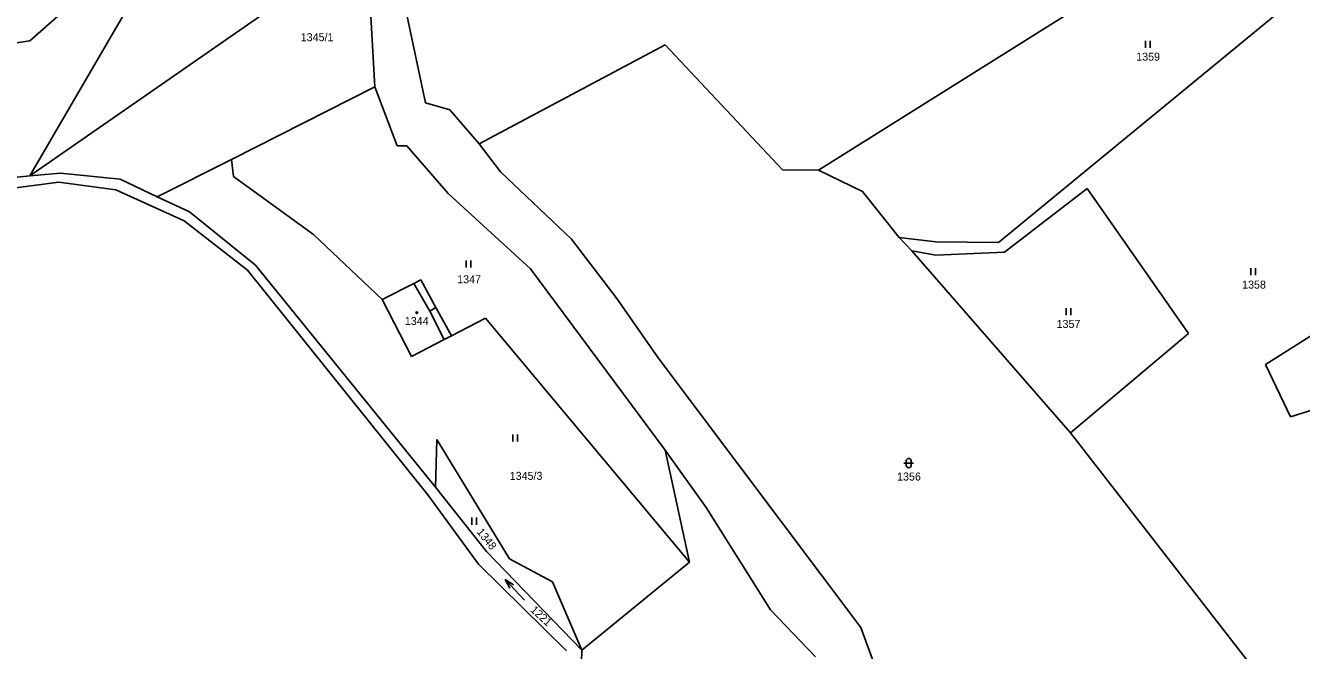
# Model space of a CAD drawing. Extents: x -670359 to -668019, y -978807 to -976674.
# Drawn here: x -669846.5 to -669575.5, y -978251.2 to -978118.6 of the extents above; entities that cross this region are included whole.
import ezdxf

# ---------------------------------------------------------------- set-up
doc = ezdxf.new("R2010")
doc.units = 0
for name, color, linetype in [('Hranice kat_území', 7, 'Continuous'), ('Hranice parcel', 7, 'Continuous'), ('Parcelní čísla', 7, 'Continuous'), ('Vnitřní kresba', 7, 'Continuous'), ('Značky budov', 7, 'Continuous'), ('Značky kultur', 7, 'Continuous')]:
    doc.layers.add(name, color=color, linetype=linetype)

msp = doc.modelspace()

# ---------------------------------------------------------------- linework, layer by layer
at = {"layer": 'Hranice kat_území'}
for points in [[(-669877.35, -978156.82), (-669839.43, -978151.83)], [(-669839.43, -978151.83), (-669827.35, -978153.5)], [(-669827.35, -978153.5), (-669812.86, -978160.03)], [(-669812.86, -978160.03), (-669799.41, -978170.5)], [(-669799.41, -978170.5), (-669761.06, -978218.21)], [(-669761.06, -978218.21), (-669750.32, -978232.95)], [(-669750.32, -978232.95), (-669731.63, -978251.32)]]:
    msp.add_lwpolyline(points, dxfattribs=at)
at = {"layer": 'Hranice parcel'}
for p, q in [((-669772.32, -978131.64), (-669802.8, -978147.01)), ((-669802.8, -978147.01), (-669818.54, -978154.94)), ((-669818.54, -978154.94), (-669811.72, -978158.16))]:
    msp.add_line(p, q, dxfattribs=at)
for points in [[(-669774.52, -978092.81), (-669772.32, -978131.64)], [(-669558.06, -978097.42), (-669639.86, -978164.68)], [(-669614.14, -978109.21), (-669678.12, -978149.31)], [(-669794.07, -978114.79), (-669845.64, -978150.52)], [(-669824.89, -978114.93), (-669845.64, -978150.52)], [(-669836.81, -978114.16), (-669845.61, -978121.83)], [(-669761.6, -978134.99), (-669765.74, -978115.32)], [(-669845.61, -978121.83), (-669855.63, -978123.32)], [(-669710.67, -978122.7), (-669750.19, -978143.73)], [(-669685.72, -978149.2), (-669710.67, -978122.7)], [(-669767.58, -978144.13), (-669772.32, -978131.64)], [(-669756.43, -978136.47), (-669761.6, -978134.99)], [(-669750.19, -978143.73), (-669756.43, -978136.47)], [(-669765.56, -978144.1), (-669767.58, -978144.13)], [(-669756.78, -978154.22), (-669765.56, -978144.1)], [(-669745.61, -978149.62), (-669750.19, -978143.73)], [(-669802.8, -978147.01), (-669802.37, -978150.61)], [(-669857.01, -978151.67), (-669845.64, -978150.52)], [(-669839.12, -978149.91), (-669845.64, -978150.52)], [(-669826.41, -978151.23), (-669839.12, -978149.91)], [(-669802.37, -978150.61), (-669785.37, -978162.95)], [(-669730.55, -978163.93), (-669745.61, -978149.62)], [(-669678.12, -978149.31), (-669685.72, -978149.2)], [(-669678.12, -978149.31), (-669668.72, -978153.81)], [(-669818.54, -978154.94), (-669826.41, -978151.23)], [(-669638.6, -978166.69), (-669621.01, -978153.21)], [(-669621.01, -978153.21), (-669599.48, -978183.99)], [(-669739.26, -978170.25), (-669756.78, -978154.22)], [(-669668.72, -978153.81), (-669660.98, -978163.57)], [(-669797.68, -978169.44), (-669811.72, -978158.16)], [(-669785.37, -978162.95), (-669770.79, -978176.78)], [(-669720.94, -978176.56), (-669730.55, -978163.93)], [(-669660.98, -978163.57), (-669658.29, -978166.4)], [(-669653.15, -978164.54), (-669660.98, -978163.57)], [(-669658.29, -978166.4), (-669624.52, -978205.08)], [(-669658.29, -978166.4), (-669653.18, -978167.34)], [(-669653.18, -978167.34), (-669638.6, -978166.69)], [(-669639.86, -978164.68), (-669653.15, -978164.54)], [(-669543.74, -978165.72), (-669583.14, -978190.57)], [(-669759.47, -978216.56), (-669797.68, -978169.44)], [(-669710.69, -978208.71), (-669739.26, -978170.25)], [(-669764.03, -978173.34), (-669770.79, -978176.78)], [(-669762.55, -978172.59), (-669764.03, -978173.34)], [(-669759.36, -978178.43), (-669762.55, -978172.59)], [(-669770.79, -978176.78), (-669764.51, -978188.85)], [(-669712.16, -978189.1), (-669720.94, -978176.56)], [(-669756.06, -978184.46), (-669759.36, -978178.43)], [(-669756.06, -978184.46), (-669748.81, -978180.7)], [(-669748.81, -978180.7), (-669705.5, -978232.52)], [(-669764.51, -978188.85), (-669757.59, -978185.25)], [(-669757.59, -978185.25), (-669756.06, -978184.46)], [(-669599.48, -978183.99), (-669624.52, -978205.08)], [(-669669.06, -978246.35), (-669712.16, -978189.1)], [(-669583.14, -978190.57), (-669577.81, -978201.66)], [(-669577.81, -978201.66), (-669551.47, -978193.39)], [(-669759.17, -978206.5), (-669759.47, -978216.56)], [(-669743.75, -978231.79), (-669759.17, -978206.5)], [(-669572.87, -978271.54), (-669624.52, -978205.08)], [(-669701.93, -978220.88), (-669710.69, -978208.71)], [(-669710.69, -978208.71), (-669705.5, -978232.52)], [(-669748.6, -978230.23), (-669759.47, -978216.56)], [(-669688.31, -978242.62), (-669701.93, -978220.88)], [(-669728.36, -978251.17), (-669748.6, -978230.23)], [(-669734.6, -978236.68), (-669743.75, -978231.79)], [(-669705.5, -978232.52), (-669728.36, -978251.17)], [(-669728.36, -978251.17), (-669734.6, -978236.68)], [(-669678.72, -978252.62), (-669688.31, -978242.62)], [(-669665.94, -978255.08), (-669669.06, -978246.35)], [(-669728.54, -978258.84), (-669728.36, -978251.17)]]:
    msp.add_lwpolyline(points, dxfattribs=at)
at = {"layer": 'Vnitřní kresba'}
for points in [[(-669764.03, -978173.34), (-669760.65, -978179.21)], [(-669760.65, -978179.21), (-669759.36, -978178.43)], [(-669760.65, -978179.21), (-669757.59, -978185.25)]]:
    msp.add_lwpolyline(points, dxfattribs=at)
at = {"layer": 'Značky budov'}
msp.add_circle((-669763.42, -978179.55), 0.175, dxfattribs=at)
at = {"layer": 'Značky kultur'}
for p, q in [((-669608.64, -978121.85), (-669608.64, -978123.35)), ((-669607.64, -978123.35), (-669607.64, -978121.85)), ((-669752.95, -978168.46), (-669752.95, -978169.96)), ((-669751.95, -978169.96), (-669751.95, -978168.46)), ((-669586.26, -978170.08), (-669586.26, -978171.58)), ((-669585.26, -978171.58), (-669585.26, -978170.08)), ((-669625.51, -978178.59), (-669625.51, -978180.09)), ((-669624.51, -978180.09), (-669624.51, -978178.59)), ((-669743.03, -978205.42), (-669743.03, -978206.92)), ((-669742.03, -978206.92), (-669742.03, -978205.42)), ((-669659.93, -978211.48), (-669657.93, -978211.48)), ((-669659.43, -978210.98), (-669659.43, -978211.98)), ((-669658.43, -978210.98), (-669658.43, -978211.98)), ((-669751.74, -978223.05), (-669751.74, -978224.55)), ((-669750.74, -978224.55), (-669750.74, -978223.05)), ((-669740.54, -978240.59), (-669744.62, -978236.19))]:
    msp.add_line(p, q, dxfattribs=at)
msp.add_lwpolyline([(-669743.63, -978238), (-669744.62, -978236.19), (-669742.9, -978237.32)], dxfattribs=at)
msp.add_circle((-669763.42, -978179.55), 0.175, dxfattribs=at)
for centre, start, end in [((-669658.93, -978210.98), 0, 180), ((-669658.93, -978211.98), 180, 0)]:
    msp.add_arc(centre, 0.5, start, end, dxfattribs=at)

# ---------------------------------------------------------------- texts
at = {"layer": 'Parcelní čísla'}
for s, p in [('1345/1', (-669788.07, -978121.92)), ('1359', (-669610.6, -978126.05)), ('1347', (-669754.84, -978173.31)), ('1358', (-669588.1, -978174.44)), ('1344', (-669765.96, -978182.15)), ('1357', (-669627.51, -978182.79)), ('1345/3', (-669743.68, -978215.03)), ('1356', (-669661.39, -978215.18))]:
    msp.add_text(s, height=1.7, dxfattribs=at).set_placement(p)
for s, rotation, p in [('1348', 308.6767, (-669750.79, -978226.12)), ('1221', 317.447, (-669739.42, -978242.82))]:
    msp.add_text(s, height=1.7, rotation=rotation, dxfattribs=at).set_placement(p)

doc.saveas('drawing.dxf')
